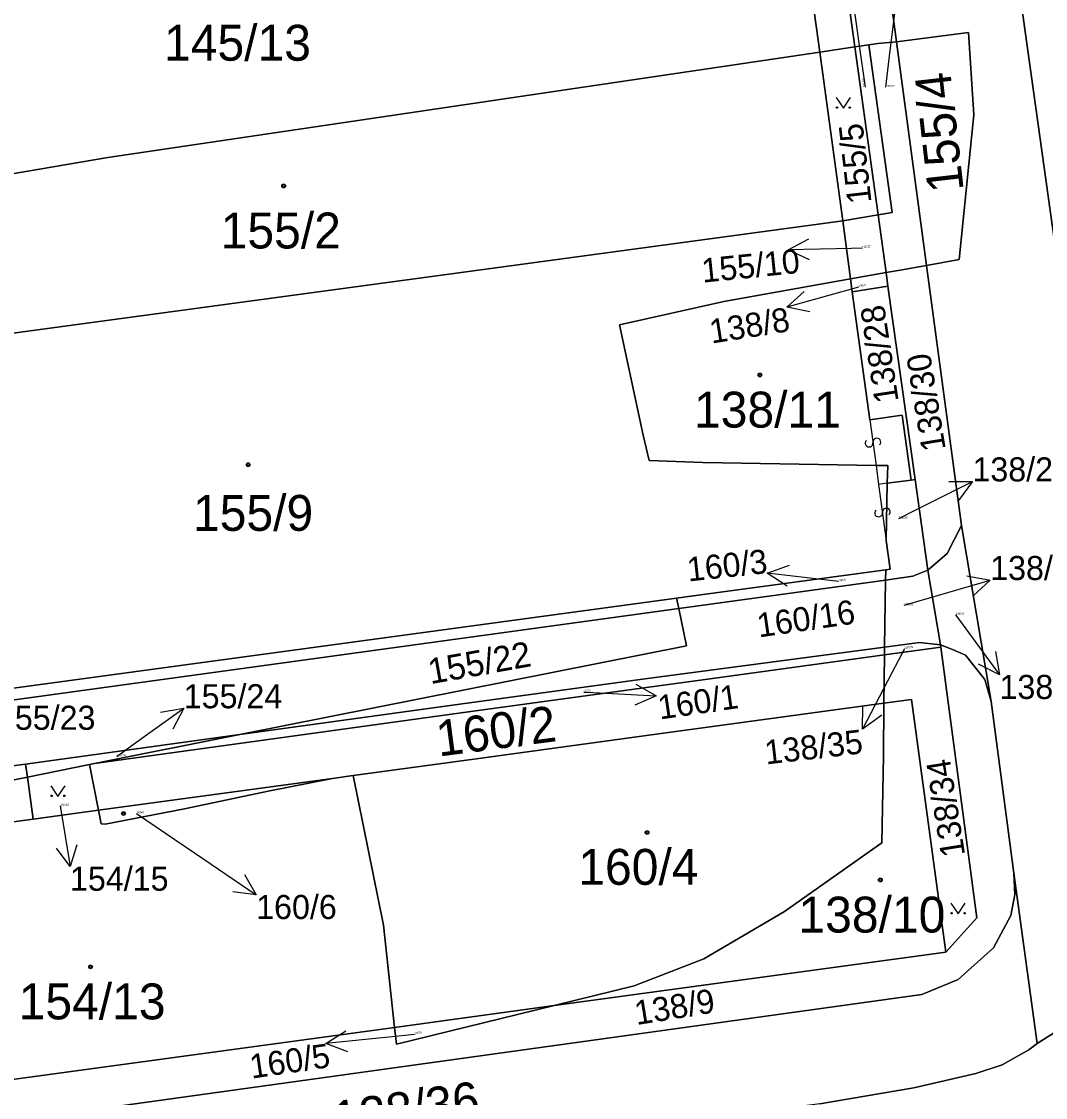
# Model space of a CAD drawing. Extents: x -600309 to -598967, y -1161267 to -1160292.
# Drawn here: x -599199.9 to -599151.4, y -1160714.1 to -1160663.1 of the extents above; entities that cross this region are included whole.
import ezdxf

# ---------------------------------------------------------------- set-up
doc = ezdxf.new("R2010")
doc.units = 0
for name, color, linetype in [('Level 1', 7, 'Continuous'), ('Level 13', 7, 'Continuous'), ('Level 3', 7, 'Continuous'), ('Level 4', 7, 'Continuous'), ('Level 5', 7, 'Continuous'), ('Level 57', 7, 'Continuous'), ('Level 60', 7, 'Continuous')]:
    doc.layers.add(name, color=color, linetype=linetype)

msp = doc.modelspace()

# ---------------------------------------------------------------- linework, layer by layer
at = {"layer": 'Level 1'}
for points in [[(-599155.14, -1160643.71), (-599149.97, -1160680.67), (-599146.38, -1160706.6)], [(-599164.31, -1160644.93), (-599163.13, -1160645.39), (-599161.94, -1160646.15), (-599161.11, -1160647.45), (-599160.59, -1160648.74), (-599160.37, -1160649.68), (-599158.44, -1160664.1)], [(-599168.42, -1160647.05), (-599166.39, -1160646.68), (-599164.49, -1160646.89), (-599163.21, -1160647.86), (-599162.5, -1160649.28), (-599160.42, -1160664.34)], [(-599162.08, -1160664.59), (-599163.36, -1160655.28), (-599168.05, -1160655.92)], [(-599159.75, -1160664.24), (-599159.33, -1160664.18), (-599158.44, -1160664.1)], [(-599158.44, -1160664.1), (-599155.04, -1160663.66), (-599154.79, -1160667.56), (-599155.48, -1160674.4), (-599157.02, -1160674.68)], [(-599158.44, -1160664.1), (-599157.02, -1160674.68)], [(-599162.08, -1160664.59), (-599195.77, -1160669.58), (-599217.41, -1160673.27)], [(-599160.42, -1160664.34), (-599162.08, -1160664.59)], [(-599160.99, -1160672.57), (-599162.08, -1160664.59)], [(-599159.75, -1160664.24), (-599160.42, -1160664.34)], [(-599160.42, -1160664.34), (-599159.32, -1160672.28)], [(-599159.75, -1160664.24), (-599158.65, -1160672.17), (-599159.32, -1160672.28)], [(-599159.32, -1160672.28), (-599160.99, -1160672.57)], [(-599158.94, -1160675.02), (-599159.32, -1160672.28)], [(-599216.47, -1160680.09), (-599160.99, -1160672.57)], [(-599160.99, -1160672.57), (-599160.62, -1160675.32)], [(-599157.02, -1160674.68), (-599158.27, -1160674.9), (-599158.94, -1160675.02)], [(-599155.37, -1160686.99), (-599157.02, -1160674.68)], [(-599159.41, -1160684.15), (-599167.61, -1160684.01), (-599170.15, -1160683.92), (-599170.43, -1160682.72), (-599171.56, -1160677.5), (-599166.62, -1160676.39), (-599160.62, -1160675.32)], [(-599160.62, -1160675.32), (-599158.94, -1160675.02)], [(-599160.62, -1160675.32), (-599160.54, -1160675.94)], [(-599158.94, -1160675.02), (-599158.85, -1160675.67)], [(-599158.85, -1160675.67), (-599160.54, -1160675.94)], [(-599158.85, -1160675.67), (-599157.56, -1160684.82)], [(-599160.54, -1160675.94), (-599159.71, -1160681.99)], [(-599216.47, -1160680.09), (-599215.48, -1160687.27), (-599214.91, -1160691.42), (-599214.2, -1160696.59), (-599168.85, -1160690.44)], [(-599159.71, -1160681.99), (-599158.17, -1160681.78), (-599157.75, -1160684.85)], [(-599158.88, -1160685), (-599158.86, -1160684.16), (-599159.41, -1160684.15)], [(-599158.93, -1160687.71), (-599158.88, -1160685)], [(-599157.75, -1160684.85), (-599158.88, -1160685)], [(-599157.75, -1160684.85), (-599157.56, -1160684.82)], [(-599157.56, -1160684.82), (-599156.96, -1160689.11)], [(-599156.96, -1160689.11), (-599156.04, -1160688.33), (-599155.37, -1160686.99)], [(-599155.37, -1160686.99), (-599153.97, -1160695.33)], [(-599158.95, -1160689.1), (-599158.74, -1160689.07), (-599158.93, -1160687.71)], [(-599168.85, -1160690.44), (-599167.59, -1160690.27), (-599158.95, -1160689.1)], [(-599158.95, -1160689.1), (-599158.96, -1160689.58)], [(-599156.96, -1160689.11), (-599157.67, -1160689.4), (-599158.96, -1160689.58)], [(-599156.96, -1160689.11), (-599156.36, -1160692.65)], [(-599168.75, -1160690.93), (-599167.59, -1160690.77), (-599158.96, -1160689.58)], [(-599159.02, -1160692.75), (-599158.96, -1160689.58)], [(-599168.85, -1160690.44), (-599168.75, -1160690.93)], [(-599168.75, -1160690.93), (-599202.61, -1160695.59)], [(-599168.75, -1160690.93), (-599168.39, -1160692.7), (-599189.52, -1160696.9)], [(-599156.36, -1160692.65), (-599157.36, -1160692.53), (-599159.02, -1160692.75)], [(-599153.97, -1160695.33), (-599154.26, -1160694.29), (-599155.18, -1160693.13), (-599155.8, -1160692.87), (-599156.16, -1160692.73), (-599156.36, -1160692.65)], [(-599156.35, -1160692.75), (-599156.36, -1160692.65)], [(-599159.02, -1160693.12), (-599167.61, -1160694.3), (-599170.17, -1160694.65), (-599178.59, -1160695.81), (-599196.4, -1160698.27)], [(-599159.02, -1160692.75), (-599170.23, -1160694.24), (-599178.66, -1160695.4), (-599189.52, -1160696.9)], [(-599159.04, -1160695.41), (-599159.02, -1160693.12)], [(-599159.02, -1160693.12), (-599156.35, -1160692.75)], [(-599159.02, -1160693.12), (-599159.02, -1160692.75)], [(-599156.11, -1160707.2), (-599154.64, -1160705.58), (-599156.35, -1160692.75)], [(-599159.04, -1160695.41), (-599169.82, -1160696.88), (-599178.22, -1160698.03), (-599184.16, -1160698.84)], [(-599174.64, -1160709.73), (-599170.86, -1160708.8), (-599167.56, -1160707.52), (-599163.75, -1160705.27), (-599159.14, -1160702.02), (-599159.06, -1160697.91), (-599159.04, -1160695.41)], [(-599159.04, -1160695.41), (-599157.74, -1160695.23), (-599156.11, -1160707.2)], [(-599152.89, -1160703.46), (-599153.97, -1160695.33)], [(-599189.52, -1160696.9), (-599199.67, -1160698.29)], [(-599189.52, -1160696.9), (-599196.4, -1160698.27)], [(-599196.4, -1160698.27), (-599196.64, -1160698.32)], [(-599202.16, -1160698.62), (-599199.67, -1160698.29)], [(-599199.67, -1160698.29), (-599199.58, -1160698.91)], [(-599199.58, -1160698.91), (-599196.64, -1160698.32)], [(-599196.64, -1160698.32), (-599196.21, -1160700.48)], [(-599202.04, -1160699.4), (-599199.58, -1160698.91)], [(-599199.58, -1160698.91), (-599199.31, -1160700.9)], [(-599196.21, -1160700.48), (-599196.08, -1160701.12), (-599195.89, -1160701.13), (-599192.14, -1160700.41), (-599188.19, -1160699.58), (-599185.14, -1160698.97)], [(-599185.14, -1160698.97), (-599196.21, -1160700.48)], [(-599184.16, -1160698.84), (-599185.14, -1160698.97)], [(-599184.16, -1160698.84), (-599182.73, -1160705.92), (-599182.2, -1160710.76)], [(-599199.31, -1160700.9), (-599196.21, -1160700.48)], [(-599201.76, -1160701.24), (-599199.31, -1160700.9)], [(-599152.89, -1160703.46), (-599152.84, -1160704.47), (-599153.04, -1160705.47), (-599153.86, -1160706.99), (-599155.52, -1160708.49), (-599157.24, -1160709.21), (-599211.64, -1160716.77)], [(-599151.79, -1160711.52), (-599152.89, -1160703.46)], [(-599146.38, -1160706.6), (-599141.88, -1160712.6), (-599141.16, -1160716.75), (-599145.42, -1160717.36), (-599146.24, -1160712.68), (-599146.84, -1160711.81), (-599147.67, -1160711.15), (-599148.83, -1160710.71), (-599150, -1160710.66), (-599151.02, -1160711.03), (-599151.79, -1160711.52)], [(-599174.64, -1160709.73), (-599156.11, -1160707.2)], [(-599174.64, -1160709.73), (-599182.11, -1160711.56), (-599182.2, -1160710.76)], [(-599182.2, -1160710.76), (-599174.64, -1160709.73)], [(-599211.9, -1160714.81), (-599182.2, -1160710.76)], [(-599162.07, -1160714.38), (-599157.63, -1160713.62), (-599154.69, -1160712.94), (-599153.45, -1160712.53), (-599152.18, -1160711.82), (-599151.79, -1160711.52)]]:
    msp.add_lwpolyline(points, dxfattribs=at)
at = {"layer": 'Level 13'}
for centre, start, end in [((-599159.742, -1160683.095), 135.0654, 7.6554), ((-599159.377, -1160683.046), 315.2799, 187.3779), ((-599159.292, -1160686.404), 134.8945, 7.4845), ((-599158.927, -1160686.357), 315.109, 187.207)]:
    msp.add_arc(centre, 0.184, start, end, dxfattribs=at)
at = {"layer": 'Level 3'}
for points in [[(-599159.71, -1160681.99), (-599159.41, -1160684.15)], [(-599159.41, -1160684.15), (-599159.29, -1160685.06)], [(-599158.88, -1160685), (-599159.29, -1160685.06)], [(-599159.29, -1160685.06), (-599158.93, -1160687.71)]]:
    msp.add_lwpolyline(points, dxfattribs=at)
at = {"layer": 'Level 5'}
for points in [[(-599161.301, -1160666.73), (-599160.96, -1160667.24), (-599160.62, -1160666.73)], [(-599198.471, -1160699.32), (-599198.13, -1160699.83), (-599197.79, -1160699.32)], [(-599155.871, -1160704.88), (-599155.53, -1160705.39), (-599155.19, -1160704.88)]]:
    msp.add_lwpolyline(points, dxfattribs=at)
for centre, radius in [((-599161.266, -1160667.206), 0.034), ((-599160.655, -1160667.206), 0.034), ((-599187.45, -1160670.92), 0.09), ((-599187.45, -1160670.92), 0.0521), ((-599164.91, -1160679.87), 0.09), ((-599164.91, -1160679.87), 0.0521), ((-599189.13, -1160684.12), 0.09), ((-599189.13, -1160684.12), 0.0521), ((-599198.436, -1160699.796), 0.034), ((-599197.825, -1160699.796), 0.034), ((-599195.03, -1160700.63), 0.09), ((-599195.03, -1160700.63), 0.0521), ((-599170.25, -1160701.53), 0.09), ((-599170.25, -1160701.53), 0.0521), ((-599159.21, -1160703.78), 0.09), ((-599159.21, -1160703.78), 0.0521), ((-599155.836, -1160705.356), 0.034), ((-599155.225, -1160705.356), 0.034), ((-599196.59, -1160707.89), 0.09), ((-599196.59, -1160707.89), 0.0521)]:
    msp.add_circle(centre, radius, dxfattribs=at)
at = {"layer": 'Level 57'}
for p, q in [((-599160.206, -1160664.167), (-599160.617, -1160661.195)), ((-599158.754, -1160664.638), (-599158.39, -1160661.66)), ((-599159.92, -1160666.24), (-599160.206, -1160664.167)), ((-599158.95, -1160666.24), (-599158.754, -1160664.638)), ((-599160.58, -1160673.881), (-599163.579, -1160673.945)), ((-599160.07, -1160673.87), (-599160.58, -1160673.881)), ((-599160.751, -1160675.853), (-599163.64, -1160676.66)), ((-599160.24, -1160675.71), (-599160.751, -1160675.853)), ((-599157.529, -1160686.261), (-599154.85, -1160684.91)), ((-599158.34, -1160686.67), (-599157.529, -1160686.261)), ((-599161.58, -1160689.604), (-599164.559, -1160689.25)), ((-599161.19, -1160689.65), (-599161.58, -1160689.604)), ((-599156.891, -1160690.422), (-599154.012, -1160689.58)), ((-599158.08, -1160690.77), (-599156.891, -1160690.422)), ((-599155.66, -1160691.22), (-599155.344, -1160691.651)), ((-599155.344, -1160691.651), (-599153.57, -1160694.07)), ((-599158.07, -1160692.84), (-599158.664, -1160693.979)), ((-599158.664, -1160693.979), (-599160.05, -1160696.64)), ((-599173.25, -1160694.89), (-599172.809, -1160694.911)), ((-599172.809, -1160694.911), (-599169.812, -1160695.055)), ((-599194.615, -1160697.401), (-599192.179, -1160695.65)), ((-599195.35, -1160697.93), (-599194.615, -1160697.401)), ((-599198.02, -1160700.27), (-599197.561, -1160703.15)), ((-599194.41, -1160700.63), (-599191.229, -1160702.8)), ((-599191.229, -1160702.8), (-599188.751, -1160704.49)), ((-599182.472, -1160711.216), (-599185.456, -1160711.524)), ((-599181.25, -1160711.09), (-599182.472, -1160711.216))]:
    msp.add_line(p, q, dxfattribs=at)
for points in [[(-599162.569, -1160674.424), (-599163.579, -1160673.945), (-599162.59, -1160673.424)], [(-599162.543, -1160676.873), (-599163.64, -1160676.66), (-599162.812, -1160675.91)], [(-599155.968, -1160684.914), (-599154.85, -1160684.91), (-599155.518, -1160685.807)], [(-599163.625, -1160689.865), (-599164.559, -1160689.25), (-599163.507, -1160688.872)], [(-599155.112, -1160689.381), (-599154.012, -1160689.58), (-599154.831, -1160690.34)], [(-599153.758, -1160692.968), (-599153.57, -1160694.07), (-599154.564, -1160693.559)], [(-599170.787, -1160694.508), (-599169.812, -1160695.055), (-599170.835, -1160695.507)], [(-599193.283, -1160695.828), (-599192.179, -1160695.65), (-599192.699, -1160696.639)], [(-599159.145, -1160695.984), (-599160.05, -1160696.64), (-599160.032, -1160695.522)], [(-599197.234, -1160702.113), (-599197.561, -1160703.15), (-599198.194, -1160702.267)], [(-599189.295, -1160703.514), (-599188.751, -1160704.49), (-599189.858, -1160704.34)], [(-599184.41, -1160711.918), (-599185.456, -1160711.524), (-599184.513, -1160710.924)]]:
    msp.add_lwpolyline(points, dxfattribs=at)
at = {"layer": 'Level 60'}
for points in [[(-599149.97, -1160680.67), (-599155.14, -1160643.71), (-599150.69, -1160643.12), (-599144.64, -1160686.61), (-599141.92, -1160705.96), (-599146.38, -1160706.6)], [(-599167.58, -1160644.87), (-599166.56, -1160644.72), (-599165.53, -1160644.67), (-599164.31, -1160644.93), (-599163.13, -1160645.39), (-599161.94, -1160646.15), (-599161.11, -1160647.45), (-599160.59, -1160648.74), (-599160.37, -1160649.68), (-599158.44, -1160664.1), (-599159.33, -1160664.18), (-599159.75, -1160664.24), (-599160.42, -1160664.34), (-599162.5, -1160649.28), (-599163.21, -1160647.86), (-599164.49, -1160646.89), (-599166.39, -1160646.68), (-599168.42, -1160647.05)], [(-599168.05, -1160655.92), (-599168.9, -1160649.73), (-599168.42, -1160647.05), (-599166.39, -1160646.68), (-599164.49, -1160646.89), (-599163.21, -1160647.86), (-599162.5, -1160649.28), (-599160.42, -1160664.34), (-599162.08, -1160664.59), (-599163.36, -1160655.28)], [(-599162.08, -1160664.59), (-599195.77, -1160669.58), (-599217.41, -1160673.27), (-599218.72, -1160663.71), (-599218.85, -1160662.8), (-599207.24, -1160661.23), (-599175.21, -1160656.89), (-599173.58, -1160656.66), (-599168.05, -1160655.92), (-599163.36, -1160655.28)], [(-599158.44, -1160664.1), (-599157.02, -1160674.68), (-599158.27, -1160674.9), (-599158.94, -1160675.02), (-599159.32, -1160672.28), (-599158.65, -1160672.17), (-599159.75, -1160664.24), (-599159.33, -1160664.18)], [(-599157.02, -1160674.68), (-599158.44, -1160664.1), (-599155.04, -1160663.66), (-599154.79, -1160667.56), (-599155.48, -1160674.4)], [(-599195.77, -1160669.58), (-599162.08, -1160664.59), (-599160.99, -1160672.57), (-599216.47, -1160680.09), (-599216.84, -1160677.4), (-599217.41, -1160673.27)], [(-599160.99, -1160672.57), (-599162.08, -1160664.59), (-599160.42, -1160664.34), (-599159.32, -1160672.28)], [(-599159.32, -1160672.28), (-599160.42, -1160664.34), (-599159.75, -1160664.24), (-599158.65, -1160672.17)], [(-599160.62, -1160675.32), (-599160.99, -1160672.57), (-599159.32, -1160672.28), (-599158.94, -1160675.02)], [(-599215.48, -1160687.27), (-599216.47, -1160680.09), (-599160.99, -1160672.57), (-599160.62, -1160675.32), (-599166.62, -1160676.39), (-599171.56, -1160677.5), (-599170.43, -1160682.72), (-599170.15, -1160683.92), (-599167.61, -1160684.01), (-599159.41, -1160684.15), (-599158.86, -1160684.16), (-599158.88, -1160685), (-599158.93, -1160687.71), (-599158.74, -1160689.07), (-599158.95, -1160689.1), (-599167.59, -1160690.27), (-599168.85, -1160690.44), (-599214.2, -1160696.59), (-599214.91, -1160691.42)], [(-599158.85, -1160675.67), (-599158.94, -1160675.02), (-599158.27, -1160674.9), (-599157.02, -1160674.68), (-599155.37, -1160686.99), (-599156.04, -1160688.33), (-599156.96, -1160689.11), (-599157.56, -1160684.82)], [(-599171.56, -1160677.5), (-599166.62, -1160676.39), (-599160.62, -1160675.32), (-599160.54, -1160675.94), (-599159.71, -1160681.99), (-599158.17, -1160681.78), (-599157.75, -1160684.85), (-599158.88, -1160685), (-599158.86, -1160684.16), (-599159.41, -1160684.15), (-599167.61, -1160684.01), (-599170.15, -1160683.92), (-599170.43, -1160682.72)], [(-599158.94, -1160675.02), (-599158.85, -1160675.67), (-599160.54, -1160675.94), (-599160.62, -1160675.32)], [(-599160.54, -1160675.94), (-599158.85, -1160675.67), (-599157.56, -1160684.82), (-599157.75, -1160684.85), (-599158.17, -1160681.78), (-599159.71, -1160681.99)], [(-599216.73, -1160697.54), (-599217.5, -1160691.93), (-599218.08, -1160687.77), (-599219.08, -1160680.5), (-599216.47, -1160680.09), (-599215.48, -1160687.27), (-599214.91, -1160691.42), (-599214.2, -1160696.59), (-599168.85, -1160690.44), (-599168.75, -1160690.93), (-599202.61, -1160695.59)], [(-599157.56, -1160684.82), (-599156.96, -1160689.11), (-599157.67, -1160689.4), (-599158.96, -1160689.58), (-599158.95, -1160689.1), (-599158.74, -1160689.07), (-599158.93, -1160687.71), (-599158.88, -1160685), (-599157.75, -1160684.85)], [(-599156.96, -1160689.11), (-599156.04, -1160688.33), (-599155.37, -1160686.99), (-599153.97, -1160695.33), (-599154.26, -1160694.29), (-599155.18, -1160693.13), (-599155.8, -1160692.87), (-599156.16, -1160692.73), (-599156.36, -1160692.65)], [(-599168.75, -1160690.93), (-599168.85, -1160690.44), (-599167.59, -1160690.27), (-599158.95, -1160689.1), (-599158.96, -1160689.58), (-599167.59, -1160690.77)], [(-599157.67, -1160689.4), (-599156.96, -1160689.11), (-599156.36, -1160692.65), (-599157.36, -1160692.53), (-599159.02, -1160692.75), (-599158.96, -1160689.58)], [(-599159.02, -1160692.75), (-599170.23, -1160694.24), (-599178.66, -1160695.4), (-599189.52, -1160696.9), (-599168.39, -1160692.7), (-599168.75, -1160690.93), (-599167.59, -1160690.77), (-599158.96, -1160689.58)], [(-599189.52, -1160696.9), (-599199.67, -1160698.29), (-599202.16, -1160698.62), (-599202.61, -1160695.59), (-599168.75, -1160690.93), (-599168.39, -1160692.7)], [(-599182.11, -1160711.56), (-599174.64, -1160709.73), (-599156.11, -1160707.2), (-599154.64, -1160705.58), (-599156.35, -1160692.75), (-599156.36, -1160692.65), (-599156.16, -1160692.73), (-599155.8, -1160692.87), (-599155.18, -1160693.13), (-599154.26, -1160694.29), (-599153.97, -1160695.33), (-599152.89, -1160703.46), (-599152.84, -1160704.47), (-599153.04, -1160705.47), (-599153.86, -1160706.99), (-599155.52, -1160708.49), (-599157.24, -1160709.21), (-599211.64, -1160716.77), (-599211.9, -1160714.81), (-599182.2, -1160710.76)], [(-599157.36, -1160692.53), (-599156.36, -1160692.65), (-599156.35, -1160692.75), (-599159.02, -1160693.12), (-599159.02, -1160692.75)], [(-599170.17, -1160694.65), (-599167.61, -1160694.3), (-599159.02, -1160693.12), (-599159.04, -1160695.41), (-599169.82, -1160696.88), (-599178.22, -1160698.03), (-599184.16, -1160698.84), (-599185.14, -1160698.97), (-599196.21, -1160700.48), (-599196.64, -1160698.32), (-599196.4, -1160698.27), (-599178.59, -1160695.81)], [(-599170.23, -1160694.24), (-599159.02, -1160692.75), (-599159.02, -1160693.12), (-599167.61, -1160694.3), (-599170.17, -1160694.65), (-599178.59, -1160695.81), (-599196.4, -1160698.27), (-599189.52, -1160696.9), (-599178.66, -1160695.4)], [(-599154.64, -1160705.58), (-599156.11, -1160707.2), (-599157.74, -1160695.23), (-599159.04, -1160695.41), (-599159.02, -1160693.12), (-599156.35, -1160692.75)], [(-599159.14, -1160702.02), (-599163.75, -1160705.27), (-599167.56, -1160707.52), (-599170.86, -1160708.8), (-599174.64, -1160709.73), (-599182.2, -1160710.76), (-599182.73, -1160705.92), (-599184.16, -1160698.84), (-599178.22, -1160698.03), (-599169.82, -1160696.88), (-599159.04, -1160695.41), (-599159.06, -1160697.91)], [(-599163.75, -1160705.27), (-599159.14, -1160702.02), (-599159.06, -1160697.91), (-599159.04, -1160695.41), (-599157.74, -1160695.23), (-599156.11, -1160707.2), (-599174.64, -1160709.73), (-599170.86, -1160708.8), (-599167.56, -1160707.52)], [(-599199.67, -1160698.29), (-599189.52, -1160696.9), (-599196.4, -1160698.27), (-599196.64, -1160698.32), (-599199.58, -1160698.91)], [(-599202.04, -1160699.4), (-599202.09, -1160699.05), (-599202.16, -1160698.62), (-599199.67, -1160698.29), (-599199.58, -1160698.91)], [(-599199.31, -1160700.9), (-599199.58, -1160698.91), (-599196.64, -1160698.32), (-599196.21, -1160700.48)], [(-599196.08, -1160701.12), (-599195.89, -1160701.13), (-599192.14, -1160700.41), (-599188.19, -1160699.58), (-599185.14, -1160698.97), (-599184.16, -1160698.84), (-599182.73, -1160705.92), (-599182.2, -1160710.76), (-599211.9, -1160714.81), (-599213.52, -1160702.85), (-599201.76, -1160701.24), (-599199.31, -1160700.9), (-599196.21, -1160700.48)], [(-599199.58, -1160698.91), (-599199.31, -1160700.9), (-599201.76, -1160701.24), (-599202.04, -1160699.4)], [(-599195.89, -1160701.13), (-599196.08, -1160701.12), (-599196.21, -1160700.48), (-599185.14, -1160698.97), (-599188.19, -1160699.58), (-599192.14, -1160700.41)], [(-599152.89, -1160703.46), (-599151.79, -1160711.52), (-599152.18, -1160711.82), (-599153.45, -1160712.53), (-599154.69, -1160712.94), (-599157.63, -1160713.62), (-599162.07, -1160714.38), (-599173.52, -1160715.87), (-599186.66, -1160717.69), (-599211.03, -1160721.07), (-599211.49, -1160717.86), (-599211.64, -1160716.77), (-599157.24, -1160709.21), (-599155.52, -1160708.49), (-599153.86, -1160706.99), (-599153.04, -1160705.47), (-599152.84, -1160704.47)], [(-599174.64, -1160709.73), (-599182.11, -1160711.56), (-599182.2, -1160710.76)]]:
    msp.add_lwpolyline(points, close=True, dxfattribs=at)
for points in [[(-599151.02, -1160711.03), (-599151.79, -1160711.52), (-599152.89, -1160703.46), (-599153.97, -1160695.33), (-599155.37, -1160686.99), (-599157.02, -1160674.68), (-599155.48, -1160674.4), (-599154.79, -1160667.56), (-599155.04, -1160663.66), (-599158.44, -1160664.1), (-599160.37, -1160649.68), (-599160.59, -1160648.74), (-599161.11, -1160647.45), (-599161.94, -1160646.15), (-599163.13, -1160645.39), (-599164.31, -1160644.93), (-599155.14, -1160643.71), (-599149.97, -1160680.67)], [(-599162.07, -1160714.38), (-599157.63, -1160713.62), (-599154.69, -1160712.94), (-599153.45, -1160712.53), (-599152.18, -1160711.82), (-599151.79, -1160711.52), (-599151.02, -1160711.03), (-599150, -1160710.66), (-599148.83, -1160710.71), (-599147.67, -1160711.15), (-599146.84, -1160711.81), (-599146.24, -1160712.68), (-599145.42, -1160717.36)]]:
    msp.add_lwpolyline(points, dxfattribs=at)

# ---------------------------------------------------------------- texts
at = {"layer": 'Level 4'}
for s, height, p in [('145/13', 1.7, (-599193.111, -1160664.99)), ('155/17', 0.1, (-599158.95, -1160666.24)), ('155/2', 1.7, (-599190.43, -1160673.88)), ('138/11', 1.7, (-599168.03, -1160682.36)), ('155/9', 1.7, (-599191.74, -1160687.25)), ('138/29', 0.1, (-599158.34, -1160686.67)), ('138/32', 0.1, (-599158.08, -1160690.77)), ('138/33', 0.1, (-599155.66, -1160691.22)), ('155/24', 0.1, (-599195.35, -1160697.93)), ('154/15', 0.1, (-599198.02, -1160700.27)), ('160/6', 0.1, (-599194.41, -1160700.63)), ('160/4', 1.7, (-599173.506, -1160704.01)), ('138/10', 1.7, (-599163.087, -1160706.27)), ('154/13', 1.7, (-599199.991, -1160710.38))]:
    msp.add_text(s, height=height, dxfattribs=at).set_placement(p)
for s, height, rotation, p in [('155/4', 1.7, 96.4692, (-599155.26, -1160671.12)), ('155/18', 0.1, 95.7103, (-599159.92, -1160666.24)), ('155/5', 1.14, 96.4964, (-599159.625, -1160671.695)), ('155/10', 0.1, 5.7876, (-599160.07, -1160673.87)), ('138/8', 0.1, 9.0997, (-599160.24, -1160675.71)), ('138/28', 1.14, 98.6418, (-599158.338, -1160681.106)), ('138/30', 1.14, 99.275, (-599156.111, -1160683.383)), ('160/3', 0.1, 6.1072, (-599161.19, -1160689.65)), ('160/16', 1.14, 8.2822, (-599164.96, -1160692.3)), ('155/22', 1.2, 10.1, (-599180.5, -1160694.51)), ('138/35', 0.1, 6.5642, (-599158.07, -1160692.84)), ('160/1', 0.1, 8.2712, (-599173.25, -1160694.89)), ('160/2', 1.7, 7.4789, (-599180.11, -1160697.94)), ('138/34', 1.14, 99.0899, (-599155.191, -1160702.599)), ('138/9', 1.14, 9.221, (-599170.747, -1160710.652)), ('160/5', 0.1, 8.3059, (-599181.25, -1160711.09)), ('138/36', 1.7, 8.1966, (-599184.97, -1160715.97))]:
    msp.add_text(s, height=height, rotation=rotation, dxfattribs=at).set_placement(p)
at = {"layer": 'Level 57'}
for s, rotation, p in [('155/10', 5.7876, (-599167.616, -1160675.5)), ('138/8', 9.0997, (-599167.199, -1160678.385)), ('160/3', 6.1072, (-599168.301, -1160689.65)), ('160/1', 8.2712, (-599169.649, -1160696.184)), ('138/35', 6.5642, (-599164.621, -1160698.313)), ('160/5', 8.3059, (-599188.969, -1160713.188))]:
    msp.add_text(s, height=1.14, rotation=rotation, dxfattribs=at).set_placement(p)
for s, p in [('138/29', (-599154.851, -1160684.91)), ('138/32', (-599154.012, -1160689.58)), ('138/33', (-599153.57, -1160695.21)), ('155/24', (-599192.179, -1160695.65)), ('155/23', (-599201.02, -1160696.67)), ('154/15', (-599197.561, -1160704.29)), ('160/6', (-599188.751, -1160705.63))]:
    msp.add_text(s, height=1.14, dxfattribs=at).set_placement(p)

doc.saveas('drawing.dxf')
